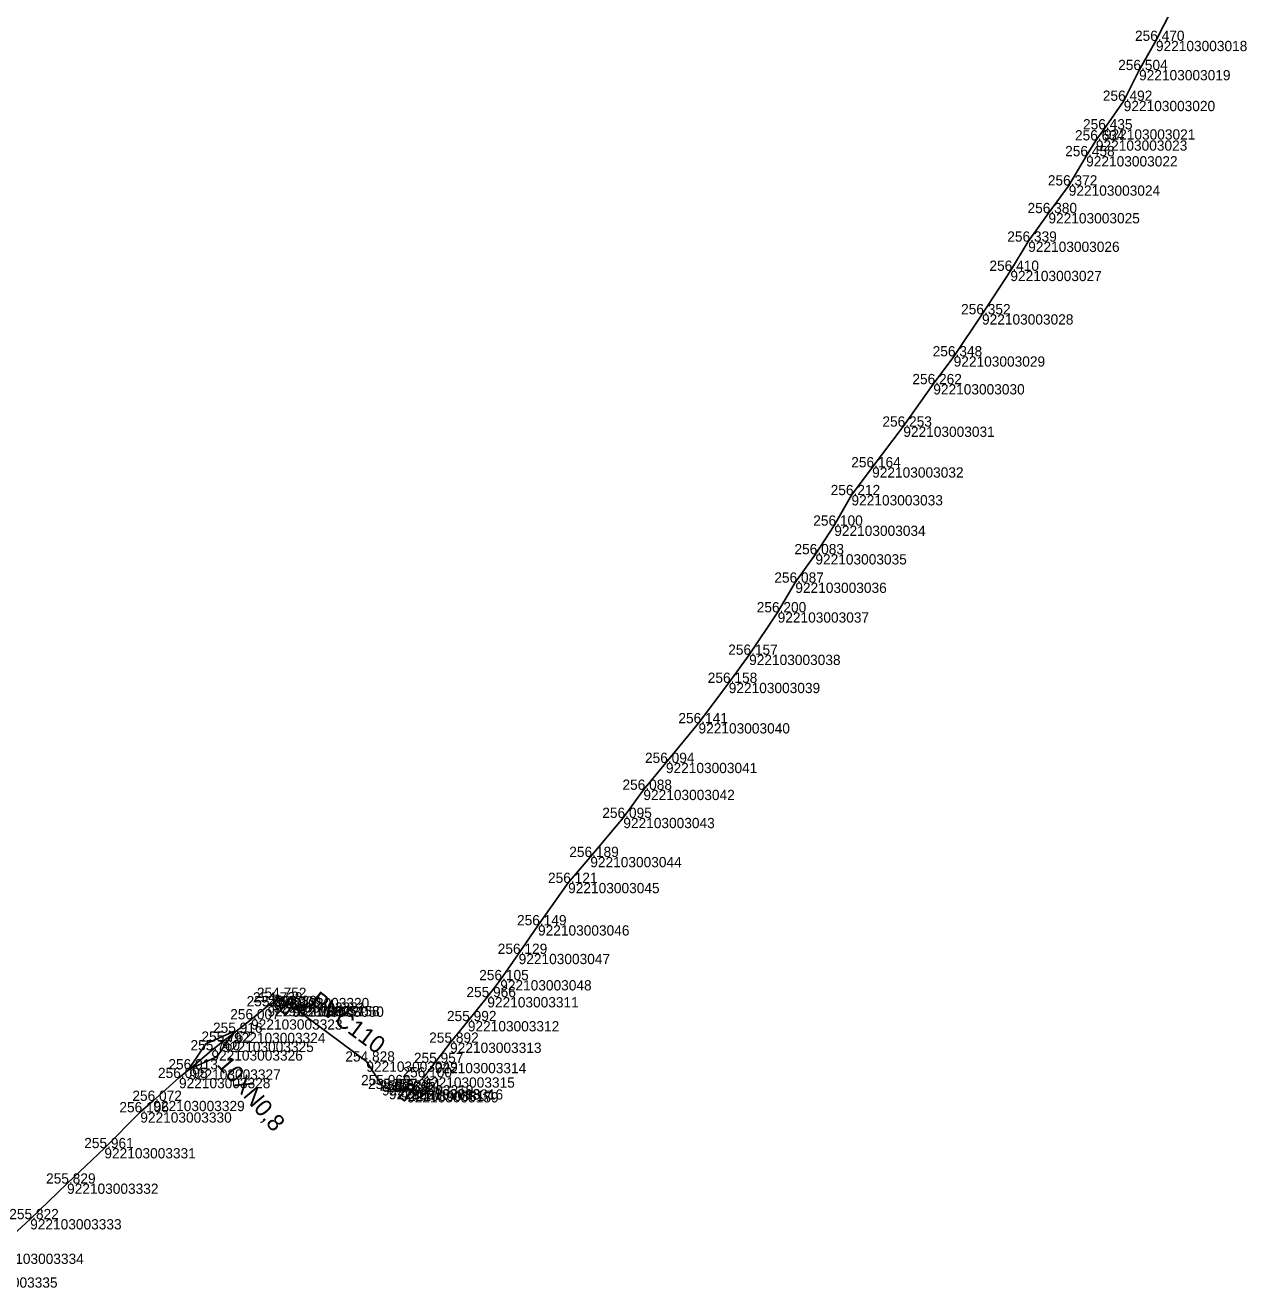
# Model space of a CAD drawing. Extents: x -771047 to -756200, y -1053876 to -1046520.
# Drawn here: x -762562.5 to -762419.4, y -1050860.4 to -1050712.5 of the extents above; entities that cross this region are included whole.
import ezdxf

# ---------------------------------------------------------------- set-up
doc = ezdxf.new("R2010")
doc.units = 0
for name, color, linetype in [('Vrstva 32', 7, 'Continuous'), ('Vrstva 33', 7, 'Continuous'), ('Vrstva 60', 7, 'Continuous'), ('Vrstva 61', 7, 'Continuous')]:
    doc.layers.add(name, color=color, linetype=linetype)

msp = doc.modelspace()

# ---------------------------------------------------------------- linework, layer by layer
at = {"layer": 'Vrstva 32'}
for points in [[(-762428.16, -1050710.63), (-762430.04, -1050714.29), (-762432.01, -1050717.71), (-762433.81, -1050721.31), (-762436.13, -1050724.66), (-762437.07, -1050725.95), (-762438.21, -1050727.8), (-762440.25, -1050731.23), (-762442.63, -1050734.47), (-762445, -1050737.81), (-762447.09, -1050741.23), (-762450.41, -1050746.32), (-762453.73, -1050751.25), (-762456.12, -1050754.51), (-762459.63, -1050759.48), (-762463.28, -1050764.25), (-762465.7, -1050767.51), (-762467.72, -1050771.08), (-762469.93, -1050774.43), (-762472.28, -1050777.76), (-762474.35, -1050781.24), (-762477.69, -1050786.21), (-762480.08, -1050789.5), (-762483.62, -1050794.23), (-762487.44, -1050798.88), (-762490.08, -1050802.03), (-762492.43, -1050805.32), (-762496.3, -1050809.9), (-762498.89, -1050812.94), (-762502.42, -1050817.9), (-762504.69, -1050821.25), (-762506.85, -1050824.33), (-762508.36, -1050826.32), (-762510.64, -1050829.13), (-762512.72, -1050831.66), (-762514.51, -1050834.03), (-762515.85, -1050835.72), (-762517.22, -1050837.12), (-762518.52, -1050837.28), (-762519.89, -1050837.08), (-762520.7, -1050836.63)], [(-762520.7, -1050836.63), (-762522.53, -1050833.86), (-762531.19, -1050827.42), (-762532.9, -1050826.41), (-762533.35, -1050826.94), (-762534.11, -1050827.39), (-762536.03, -1050828.92)], [(-762536.03, -1050828.92), (-762538.03, -1050830.5), (-762539.4, -1050831.54), (-762540.68, -1050832.55), (-762543.27, -1050834.78), (-762544.48, -1050835.79), (-762547.49, -1050838.47), (-762549.01, -1050839.81), (-762553.22, -1050844.01), (-762557.59, -1050848.16), (-762561.91, -1050852.33), (-762566.34, -1050856.37)], [(-762543.36, -1050834.8), (-762541.32, -1050831.78), (-762537.99, -1050830.3), (-762540.03, -1050833.32), (-762543.36, -1050834.8)]]:
    msp.add_lwpolyline(points, dxfattribs=at)
at = {"layer": 'Vrstva 33'}
for points in [[(-762531.37, -1050826.33), (-762530.78, -1050826.77), (-762531.98, -1050828.39), (-762532.58, -1050827.94)], [(-762517.44, -1050836.42), (-762516.85, -1050836.86), (-762518.05, -1050838.48), (-762518.65, -1050838.03)]]:
    msp.add_lwpolyline(points, close=True, dxfattribs=at)
for points in [[(-762531.1, -1050828.08), (-762530.36, -1050827.08)], [(-762530.36, -1050827.08), (-762529.94, -1050827.39)], [(-762522.53, -1050833.86), (-762531.19, -1050827.42)], [(-762530.31, -1050827.89), (-762530.73, -1050827.57)], [(-762529.94, -1050827.39), (-762529.84, -1050827.53), (-762529.87, -1050827.75), (-762529.94, -1050827.84), (-762530.15, -1050827.94), (-762530.31, -1050827.89)], [(-762517.17, -1050838.17), (-762516.42, -1050837.17)], [(-762516.42, -1050837.17), (-762516.01, -1050837.48)], [(-762516.01, -1050837.48), (-762515.91, -1050837.62), (-762515.94, -1050837.84), (-762516.01, -1050837.93), (-762516.22, -1050838.03), (-762516.38, -1050837.98)], [(-762516.38, -1050837.98), (-762516.79, -1050837.66)]]:
    msp.add_lwpolyline(points, dxfattribs=at)
at = {"layer": 'Vrstva 60'}
for p, q in [((-762430.04, -1050714.29), (-762430.04, -1050714.29)), ((-762432.01, -1050717.71), (-762432.01, -1050717.71)), ((-762433.81, -1050721.31), (-762433.81, -1050721.31)), ((-762436.13, -1050724.66), (-762436.13, -1050724.66)), ((-762437.07, -1050725.95), (-762437.07, -1050725.95)), ((-762438.21, -1050727.8), (-762438.21, -1050727.8)), ((-762440.25, -1050731.23), (-762440.25, -1050731.23)), ((-762442.63, -1050734.47), (-762442.63, -1050734.47)), ((-762445, -1050737.81), (-762445, -1050737.81)), ((-762447.09, -1050741.23), (-762447.09, -1050741.23)), ((-762450.41, -1050746.32), (-762450.41, -1050746.32)), ((-762453.73, -1050751.25), (-762453.73, -1050751.25)), ((-762456.12, -1050754.51), (-762456.12, -1050754.51)), ((-762459.63, -1050759.48), (-762459.63, -1050759.48)), ((-762463.28, -1050764.25), (-762463.28, -1050764.25)), ((-762465.7, -1050767.51), (-762465.7, -1050767.51)), ((-762467.72, -1050771.08), (-762467.72, -1050771.08)), ((-762469.93, -1050774.43), (-762469.93, -1050774.43)), ((-762472.28, -1050777.76), (-762472.28, -1050777.76)), ((-762474.35, -1050781.24), (-762474.35, -1050781.24)), ((-762477.69, -1050786.21), (-762477.69, -1050786.21)), ((-762480.08, -1050789.5), (-762480.08, -1050789.5)), ((-762483.62, -1050794.23), (-762483.62, -1050794.23)), ((-762487.44, -1050798.88), (-762487.44, -1050798.88)), ((-762490.08, -1050802.03), (-762490.08, -1050802.03)), ((-762492.43, -1050805.32), (-762492.43, -1050805.32)), ((-762496.3, -1050809.9), (-762496.3, -1050809.9)), ((-762498.89, -1050812.94), (-762498.89, -1050812.94)), ((-762502.42, -1050817.9), (-762502.42, -1050817.9)), ((-762504.69, -1050821.25), (-762504.69, -1050821.25)), ((-762506.85, -1050824.33), (-762506.85, -1050824.33)), ((-762533.35, -1050826.94), (-762533.35, -1050826.94)), ((-762532.9, -1050826.41), (-762532.9, -1050826.41)), ((-762508.36, -1050826.32), (-762508.36, -1050826.32)), ((-762534.11, -1050827.39), (-762534.11, -1050827.39)), ((-762531.68, -1050827.36), (-762531.68, -1050827.36)), ((-762531.19, -1050827.42), (-762531.19, -1050827.42)), ((-762536.03, -1050828.92), (-762536.03, -1050828.92)), ((-762510.64, -1050829.13), (-762510.64, -1050829.13)), ((-762539.4, -1050831.54), (-762539.4, -1050831.54)), ((-762538.03, -1050830.5), (-762538.03, -1050830.5)), ((-762540.68, -1050832.55), (-762540.68, -1050832.55)), ((-762512.72, -1050831.66), (-762512.72, -1050831.66)), ((-762522.53, -1050833.86), (-762522.53, -1050833.86)), ((-762514.51, -1050834.03), (-762514.51, -1050834.03)), ((-762544.48, -1050835.79), (-762544.48, -1050835.79)), ((-762543.27, -1050834.78), (-762543.27, -1050834.78)), ((-762515.85, -1050835.72), (-762515.85, -1050835.72)), ((-762520.7, -1050836.63), (-762520.7, -1050836.63)), ((-762519.89, -1050837.08), (-762519.89, -1050837.08)), ((-762518.52, -1050837.28), (-762518.52, -1050837.28)), ((-762517.75, -1050837.45), (-762517.75, -1050837.45)), ((-762517.22, -1050837.12), (-762517.22, -1050837.12)), ((-762547.49, -1050838.47), (-762547.49, -1050838.47)), ((-762549.01, -1050839.81), (-762549.01, -1050839.81)), ((-762553.22, -1050844.01), (-762553.22, -1050844.01)), ((-762557.59, -1050848.16), (-762557.59, -1050848.16)), ((-762561.91, -1050852.33), (-762561.91, -1050852.33))]:
    msp.add_line(p, q, dxfattribs=at)

# ---------------------------------------------------------------- texts
at = {"layer": 'Vrstva 32'}
msp.add_text('10XN0,8', height=2, rotation=309.986, dxfattribs=at).set_placement((-762540.12, -1050834.25))
at = {"layer": 'Vrstva 33'}
msp.add_text('PVC110', height=2, rotation=323.3606, dxfattribs=at).set_placement((-762529.28, -1050827.11))
at = {"layer": 'Vrstva 60'}
for s, p in [('922103003018', (-762430.04, -1050715.49)), ('922103003019', (-762432.01, -1050718.91)), ('922103003020', (-762433.81, -1050722.52)), ('922103003021', (-762436.13, -1050725.85)), ('922103003023', (-762437.07, -1050727.15)), ('922103003022', (-762438.21, -1050729)), ('922103003024', (-762440.25, -1050732.43)), ('922103003025', (-762442.63, -1050735.67)), ('922103003026', (-762445, -1050739.01)), ('922103003027', (-762447.09, -1050742.43)), ('922103003028', (-762450.41, -1050747.52)), ('922103003029', (-762453.73, -1050752.45)), ('922103003030', (-762456.12, -1050755.71)), ('922103003031', (-762459.63, -1050760.68)), ('922103003032', (-762463.28, -1050765.45)), ('922103003033', (-762465.7, -1050768.71)), ('922103003034', (-762467.72, -1050772.28)), ('922103003035', (-762469.93, -1050775.63)), ('922103003036', (-762472.28, -1050778.96)), ('922103003037', (-762474.35, -1050782.44)), ('922103003038', (-762477.69, -1050787.41)), ('922103003039', (-762480.08, -1050790.7)), ('922103003040', (-762483.62, -1050795.43)), ('922103003041', (-762487.44, -1050800.07)), ('922103003042', (-762490.08, -1050803.23)), ('922103003043', (-762492.43, -1050806.52)), ('922103003044', (-762496.3, -1050811.1)), ('922103003045', (-762498.89, -1050814.14)), ('922103003046', (-762502.42, -1050819.1)), ('922103003047', (-762504.69, -1050822.45)), ('922103003048', (-762506.85, -1050825.53)), ('922103003321', (-762533.35, -1050828.14)), ('922103003320', (-762532.9, -1050827.61)), ('922103003311', (-762508.36, -1050827.52)), ('922103003322', (-762534.11, -1050828.58)), ('922103005158', (-762531.68, -1050828.56)), ('922103003050', (-762531.19, -1050828.62)), ('922103003323', (-762536.03, -1050830.12)), ('922103003312', (-762510.64, -1050830.33)), ('922103003325', (-762539.4, -1050832.74)), ('922103003324', (-762538.03, -1050831.7)), ('922103003326', (-762540.68, -1050833.75)), ('922103003313', (-762512.72, -1050832.85)), ('922103003049', (-762522.53, -1050835.06)), ('922103003314', (-762514.51, -1050835.23)), ('922103003328', (-762544.48, -1050836.99)), ('922103003327', (-762543.27, -1050835.98)), ('922103003315', (-762515.85, -1050836.92)), ('922103003319', (-762520.7, -1050837.83)), ('922103003318', (-762519.89, -1050838.28)), ('922103003317', (-762518.52, -1050838.48)), ('922103005159', (-762517.75, -1050838.65)), ('922103003316', (-762517.22, -1050838.32)), ('922103003329', (-762547.49, -1050839.67)), ('922103003330', (-762549.01, -1050841.02)), ('922103003331', (-762553.22, -1050845.21)), ('922103003332', (-762557.59, -1050849.36)), ('922103003333', (-762561.91, -1050853.53)), ('922103003334', (-762566.34, -1050857.57)), ('922103003335', (-762569.41, -1050860.35))]:
    msp.add_text(s, height=1.2, dxfattribs=at).set_placement(p)
at = {"layer": 'Vrstva 61'}
for s, p in [('256.470', (-762432.49, -1050714.29)), ('256.504', (-762434.46, -1050717.71)), ('256.492', (-762436.26, -1050721.31)), ('256.435', (-762438.58, -1050724.66)), ('256.634', (-762439.52, -1050725.95)), ('256.458', (-762440.67, -1050727.8)), ('256.372', (-762442.7, -1050731.23)), ('256.380', (-762445.08, -1050734.47)), ('256.339', (-762447.45, -1050737.81)), ('256.410', (-762449.54, -1050741.23)), ('256.352', (-762452.86, -1050746.32)), ('256.348', (-762456.19, -1050751.25)), ('256.262', (-762458.57, -1050754.51)), ('256.253', (-762462.08, -1050759.48)), ('256.164', (-762465.73, -1050764.25)), ('256.212', (-762468.14, -1050767.51)), ('256.100', (-762470.18, -1050771.08)), ('256.083', (-762472.38, -1050774.43)), ('256.087', (-762474.74, -1050777.76)), ('256.200', (-762476.8, -1050781.24)), ('256.157', (-762480.14, -1050786.21)), ('256.158', (-762482.54, -1050789.5)), ('256.141', (-762485.98, -1050794.23)), ('256.094', (-762489.89, -1050798.88)), ('256.088', (-762492.53, -1050802.03)), ('256.095', (-762494.89, -1050805.32)), ('256.189', (-762498.76, -1050809.9)), ('256.121', (-762501.25, -1050812.94)), ('256.149', (-762504.88, -1050817.9)), ('256.129', (-762507.14, -1050821.25)), ('256.105', (-762509.31, -1050824.33)), ('254.752', (-762535.35, -1050826.41)), ('255.966', (-762510.81, -1050826.32)), ('255.697', (-762536.56, -1050827.39)), ('254.729', (-762535.81, -1050826.94)), ('256.689', (-762534.13, -1050827.36)), ('254.900', (-762533.64, -1050827.42)), ('256.007', (-762538.48, -1050828.92)), ('255.992', (-762513.09, -1050829.13)), ('255.916', (-762540.49, -1050830.5)), ('255.760', (-762543.13, -1050832.55)), ('255.762', (-762541.85, -1050831.54)), ('255.892', (-762515.17, -1050831.66)), ('254.828', (-762524.99, -1050833.86)), ('255.957', (-762516.96, -1050834.03)), ('256.013', (-762545.72, -1050834.78)), ('256.100', (-762518.3, -1050835.72)), ('256.095', (-762546.94, -1050835.79)), ('255.069', (-762523.15, -1050836.63)), ('255.607', (-762522.34, -1050837.08)), ('255.951', (-762519.57, -1050837.12)), ('256.072', (-762549.94, -1050838.47)), ('255.822', (-762520.97, -1050837.28)), ('256.692', (-762520.19, -1050837.45)), ('256.106', (-762551.46, -1050839.81)), ('255.961', (-762555.58, -1050844.01)), ('255.829', (-762560.05, -1050848.16)), ('255.822', (-762564.36, -1050852.33))]:
    msp.add_text(s, height=1.2, dxfattribs=at).set_placement(p)

doc.saveas('drawing.dxf')
